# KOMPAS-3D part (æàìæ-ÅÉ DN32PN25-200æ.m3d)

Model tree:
1. Объединить компоненты:2  (labels: СЕНС-ПР DN32PN25-200С)

Referenced files in D:\Савин\!СЕНСОР\3D для заказчика\!Новый перечень\СЕНС-ПР\2. СЕНС-ПР-200С\DN32\: СЕНС-ПР DN32PN25-200С.a3d
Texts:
  СЕНС-ПР DN32PN25-200С
  ООО НПП Сенсор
